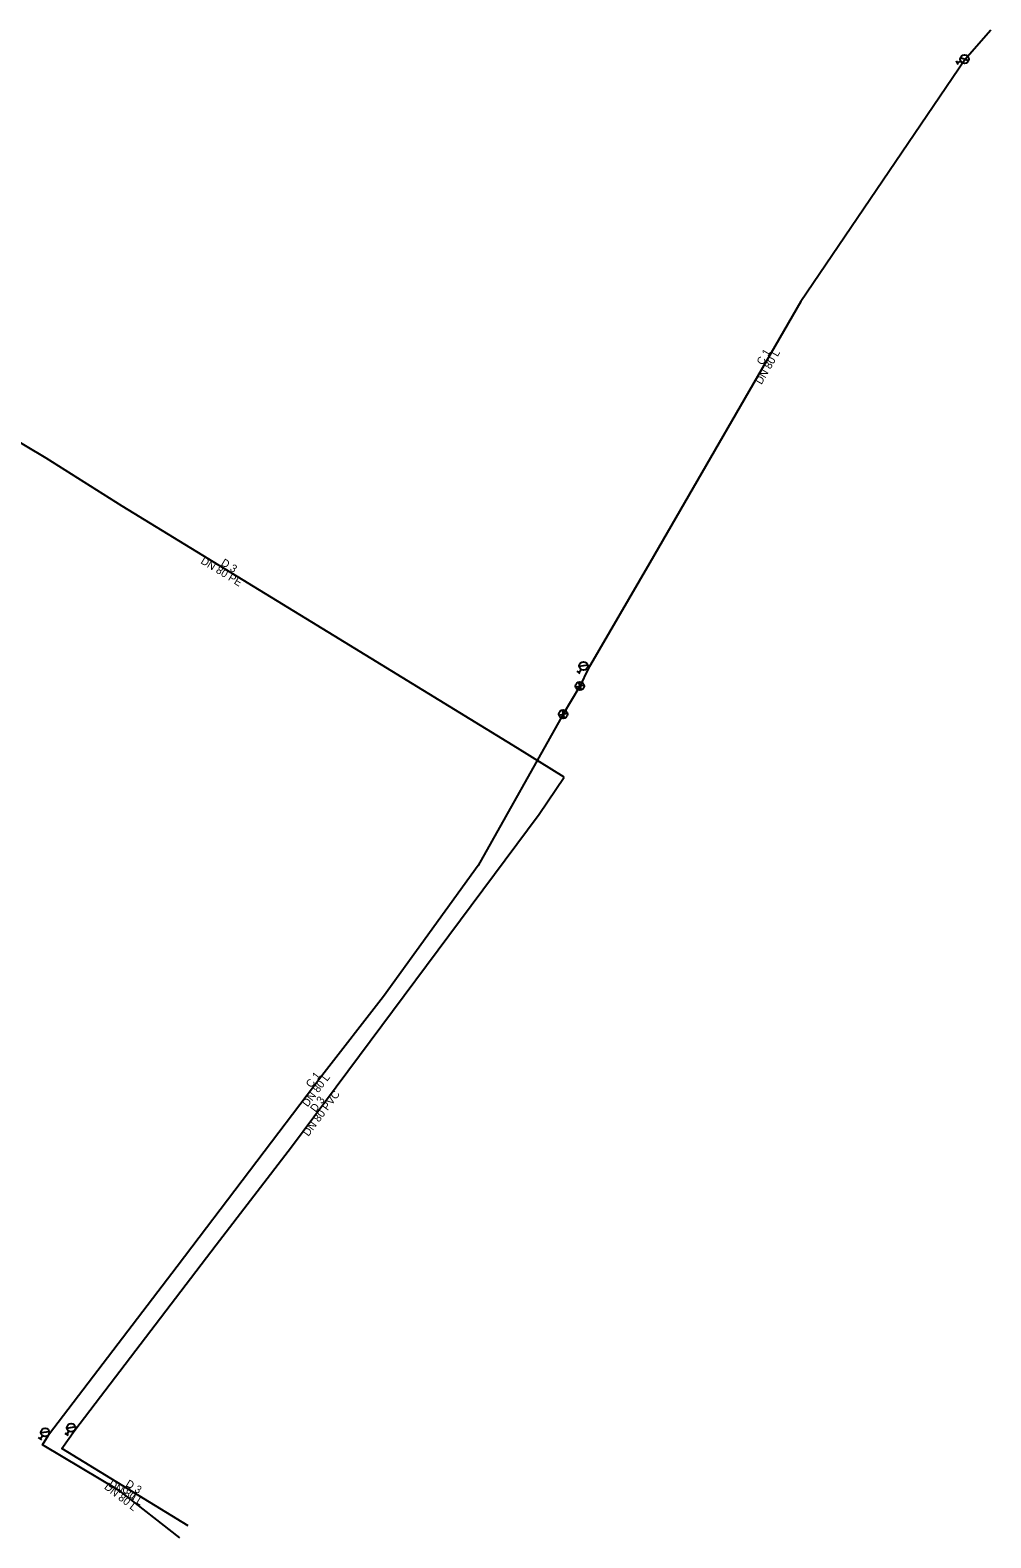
# Model space of a CAD drawing. Extents: x -600635 to -600187, y -1203951 to -1203569.
# Drawn here: x -600299.8 to -600186.7, y -1203818 to -1203640.4 of the extents above; entities that cross this region are included whole.
import ezdxf

# ---------------------------------------------------------------- set-up
doc = ezdxf.new("R2010")
doc.units = 0
for name, color, linetype in [('Default', 7, 'Continuous'), ('hydrant_v_majetku_nebo_provozovany', 7, 'Continuous'), ('popisy_rad', 7, 'Continuous'), ('rad_v_majetku', 7, 'Continuous'), ('uzaver_v_majetku_nebo_provozovany', 7, 'Continuous')]:
    doc.layers.add(name, color=color, linetype=linetype)

# ---------------------------------------------------------------- blocks, each defined once
blk = doc.blocks.new('MoSymbol 2')
at = {"layer": 'Default'}
for p, q in [((-0.000035, -0.000035), (0.000035, 0.000035)), ((0.000035, -0.000035), (-0.000035, 0.000035))]:
    blk.add_line(p, q, dxfattribs=at)
for radius in [0.00005, 0.0000025]:
    blk.add_circle((0, 0), radius, dxfattribs=at)
blk = doc.blocks.new('MoSymbol 3')
at = {"layer": 'Default'}
for p, q in [((-0.000036, -0.000036), (0.000036, 0.000036)), ((-0.000023, 0.000095), (0.000023, 0.000095)), ((0, 0.000095), (0, 0.00005))]:
    blk.add_line(p, q, dxfattribs=at)
blk.add_circle((0, 0), 0.00005, dxfattribs=at)

msp = doc.modelspace()

# ---------------------------------------------------------------- linework, layer by layer
at = {"layer": 'rad_v_majetku'}
for p, q in [((-600186.65, -1203640.41), (-600189.72, -1203643.89)), ((-600234.08, -1203715.62), (-600235.06, -1203717.65)), ((-600235.06, -1203717.65), (-600237.02, -1203720.96))]:
    msp.add_line(p, q, dxfattribs=at)
for points in [[(-600189.72, -1203643.89), (-600209.04, -1203672.38), (-600226.82, -1203703.14), (-600234.08, -1203715.62)], [(-600236.89, -1203728.36), (-600242.38, -1203724.95), (-600264, -1203711.73), (-600288.95, -1203696.47), (-600297.92, -1203690.81), (-600315.79, -1203680.19)], [(-600237.02, -1203720.96), (-600247.04, -1203738.76), (-600258.19, -1203754.2), (-600265.44, -1203763.56), (-600282.47, -1203785.99), (-600297.62, -1203805.86)], [(-600294.52, -1203805.29), (-600277.89, -1203783.47), (-600269.03, -1203771.91), (-600239.86, -1203732.74), (-600236.89, -1203728.36)], [(-600282.15, -1203817.96), (-600289.19, -1203812.47), (-600298.34, -1203807), (-600297.62, -1203805.86)], [(-600281.18, -1203816.56), (-600296.07, -1203807.44), (-600294.52, -1203805.29)]]:
    msp.add_lwpolyline(points, dxfattribs=at)

# ---------------------------------------------------------------- block references
at = {"layer": 'hydrant_v_majetku_nebo_provozovany', "xscale": 9998.75015623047, "yscale": 9998.750156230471}
for p, rotation in [((-600189.75, -1203643.83), 115.05282631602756), ((-600234.62, -1203715.28), 143.3929252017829), ((-600298.04, -1203805.54), 142.3596414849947), ((-600294.97, -1203804.99), 146.8693287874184)]:
    msp.add_blockref('MoSymbol 3', p, dxfattribs=dict(at, rotation=rotation))
at = {"layer": 'uzaver_v_majetku_nebo_provozovany'}
for p, xscale, yscale, rotation in [((-600235.06, -1203717.65), 9998.75015623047, 9998.750156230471, -118.18387761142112), ((-600237.02, -1203720.96), 9998.750156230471, 9998.75015623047, -119.97417508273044)]:
    msp.add_blockref('MoSymbol 2', p, dxfattribs=dict(at, xscale=xscale, yscale=yscale, rotation=rotation))

# ---------------------------------------------------------------- texts
at = {"layer": 'popisy_rad'}
for s, rotation, p in [('C 1', 59.9633, (-600213.51, -1203679.93)), ('DN 80 L', 59.9633, (-600213.67, -1203682.21)), ('DN 80 PE', 328.5547, (-600279.79, -1203703.14)), ('D 3', 328.5547, (-600277.39, -1203703.36)), ('C 1', 52.7794, (-600266.69, -1203765.03)), ('DN 80 L', 52.7794, (-600267.12, -1203767.28)), ('DN 80 PVC', 53.3239, (-600267.03, -1203770.75)), ('D 3', 53.3239, (-600266.17, -1203767.9)), ('DN 80 L', 328.5023, (-600290.62, -1203811.84)), ('D 3', 328.5023, (-600288.63, -1203811.82)), ('DN 80 L', 322.0653, (-600291.15, -1203812.1)), ('C 1', 322.0653, (-600289.08, -1203812.38))]:
    msp.add_text(s, height=0.91, rotation=rotation, dxfattribs=at).set_placement(p)

doc.saveas('drawing.dxf')
